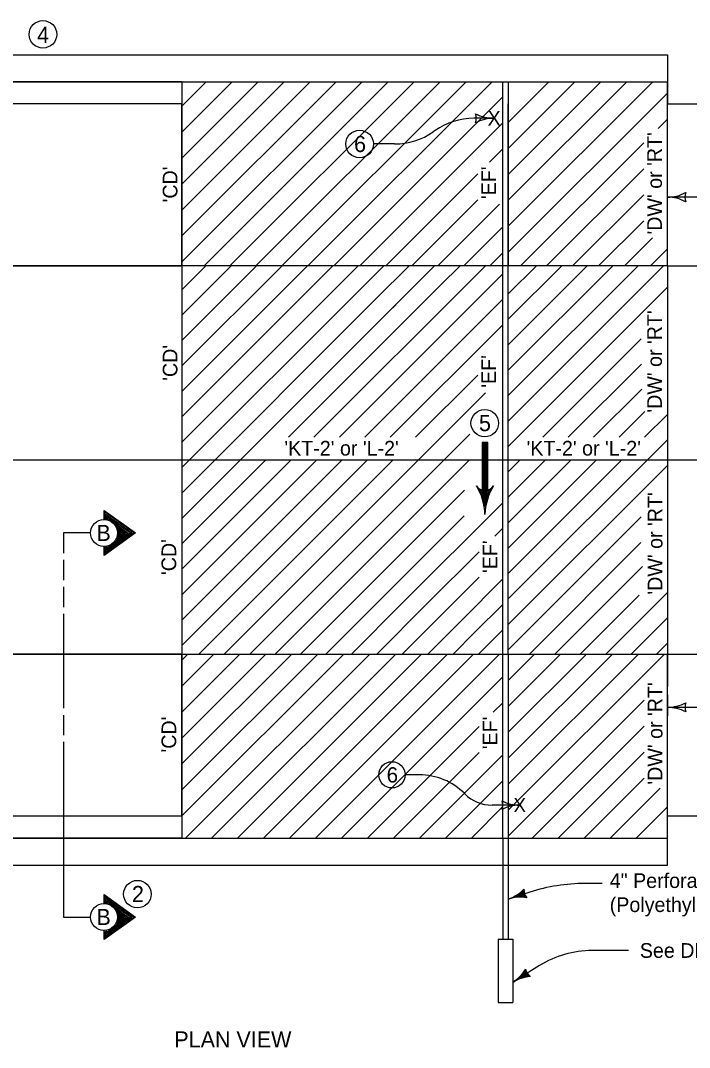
# Model space of a CAD drawing. Extents: x 10045 to 81668, y 6370 to 11018.
# Drawn here: x 14873 to 15638, y 6428 to 7602 of the extents above; entities that cross this region are included whole.
import ezdxf

# ---------------------------------------------------------------- set-up
doc = ezdxf.new("R2010")
doc.units = 0
for name, color, linetype in [('Alignment', 7, 'Continuous'), ('Default', 7, 'Continuous'), ('dsnStdLineWork', 7, 'Continuous')]:
    doc.layers.add(name, color=color, linetype=linetype)

msp = doc.modelspace()

# ---------------------------------------------------------------- linework, layer by layer
at = {"layer": 'Alignment'}
for p, q in [((15612.4, 7369.2), (15612.4, 7410.7)), ((15756.9, 7400.4), (15612.4, 7400.4)), ((15612.4, 7322), (15612.4, 6877.9)), ((15417, 6898.4), (15424.3, 6905.6)), ((14248, 6877.9), (15612.4, 6877.9)), ((15612.4, 6831.3), (15612.4, 6807.4)), ((15612.4, 6817), (15755.9, 6817)), ((14922.1, 6777.4), (14922.1, 6577.2)), ((15328.8, 6739.8), (15312.5, 6739.8)), ((15443.3, 6705.2), (15412, 6705.2)), ((15537.7, 6615.5), (15518.1, 6615.5)), ((15567.8, 6538.9), (15526.2, 6538.9)), ((15466.2, 6521.6), (15435.6, 6502.5))]:
    msp.add_line(p, q, dxfattribs=at)
for points in [[(14952.9, 7016.4), (14922.1, 7016.4), (14922.1, 6993.3)], [(14922.1, 6985.6), (14922.1, 6962.4)], [(14922.1, 6954.7), (14922.1, 6931.6)], [(14922.1, 6923.9), (14922.1, 6815.9)], [(14922.1, 6808.2), (14922.1, 6785.1)], [(14922.1, 6588.6), (14922.1, 6577.2), (14952.9, 6577.2)]]:
    msp.add_lwpolyline(points, dxfattribs=at)
for centre, radius, start, end in [((15328.8, 6666.4), 73.4, 45, 90), ((15412, 6749.2), 44.1, 225, 270), ((15518.1, 6409.9), 205.6, 90, 107.8594), ((15526.2, 6425.8), 113.1, 90, 122.0832)]:
    msp.add_arc(centre, radius, start, end, dxfattribs=at)
at = {"layer": 'Default'}
msp.add_line((14687.2, 7532.4), (15612.4, 7532.4), dxfattribs=at)
at = {"layer": 'dsnStdLineWork'}
for p, q in [((14724.2, 7563.3), (15612.4, 7563.3)), ((15612.4, 7563.3), (15612.4, 7507)), ((14687.2, 7532.4), (15057.3, 7532.4)), ((15057.3, 7532.4), (14687.2, 7532.4)), ((15057.3, 7532.4), (15057.3, 6877.9)), ((15057.3, 7326.3), (15263.5, 7532.4)), ((15057.3, 7356), (15233.8, 7532.4)), ((15057.3, 7385.7), (15204.1, 7532.4)), ((15057.3, 7415.4), (15174.4, 7532.4)), ((15057.3, 7445.1), (15144.7, 7532.4)), ((15057.3, 7474.8), (15115, 7532.4)), ((15057.3, 7504.5), (15085.3, 7532.4)), ((15082.7, 7322), (15293.2, 7532.4)), ((15112.4, 7322), (15322.9, 7532.4)), ((15142.1, 7322), (15352.6, 7532.4)), ((15171.8, 7322), (15382.3, 7532.4)), ((15201.5, 7322), (15412, 7532.4)), ((15424.3, 7322), (15424.3, 7532.4)), ((15430.4, 7532.4), (15430.4, 7322)), ((15430.4, 7367.1), (15595.7, 7532.4)), ((15430.4, 7396.8), (15566, 7532.4)), ((15430.4, 7426.5), (15536.3, 7532.4)), ((15430.4, 7456.2), (15506.6, 7532.4)), ((15430.4, 7485.9), (15476.9, 7532.4)), ((15612.4, 7322), (15612.4, 7532.4)), ((15430.4, 7337.4), (15612.4, 7519.4)), ((15057.3, 7507), (14687.3, 7507)), ((15057.3, 7322), (15057.3, 7507)), ((15057.3, 7321.9), (15057.3, 7507)), ((15231.2, 7322), (15424.3, 7515.1)), ((15424.3, 7322), (15424.3, 7507)), ((15430.4, 7322), (15430.4, 7507)), ((15612.4, 7507), (16123.2, 7507)), ((15612.4, 7322), (15612.4, 7507)), ((15260.9, 7322), (15424.3, 7485.4)), ((15414, 7490.6), (15391.2, 7490.6)), ((15601.7, 7479), (15612.4, 7489.7)), ((15347, 7476.7), (15344.7, 7475.1)), ((15300.5, 7461.2), (15276.3, 7461.2)), ((15444.6, 7322), (15585.3, 7462.6)), ((15409.1, 7440.5), (15424.3, 7455.7)), ((15290.6, 7322), (15395.8, 7427.2)), ((15474.3, 7322), (15585.3, 7432.9)), ((15504, 7322), (15585.3, 7403.2)), ((15320.3, 7322), (15395.8, 7397.5)), ((15350, 7322), (15420.3, 7392.3)), ((15379.7, 7322), (15424.3, 7366.6)), ((15533.7, 7322), (15585.3, 7373.5)), ((15563.4, 7322), (15595.2, 7353.7)), ((15612.4, 7322), (15612.4, 7359)), ((15593.1, 7322), (15612.4, 7341.2)), ((15409.4, 7322), (15424.3, 7336.9)), ((15612.4, 7322), (14201.3, 7322)), ((14687.3, 7321.9), (15057.3, 7321.9)), ((14687.3, 7321.9), (15057.3, 7321.9)), ((15057.3, 7294.6), (15084.7, 7322)), ((15057.3, 7265.5), (15113.7, 7322)), ((15057.3, 7236.4), (15142.8, 7322)), ((15057.3, 7207.4), (15171.9, 7322)), ((15057.3, 7178.3), (15201, 7322)), ((15057.3, 7149.2), (15230, 7322)), ((15057.3, 7120.1), (15259.1, 7322)), ((15057.3, 7321.9), (15057.3, 6877.9)), ((15261.9, 7295.7), (15288.2, 7322)), ((15279.3, 7284), (15317.3, 7322)), ((15305.3, 7280.9), (15346.3, 7322)), ((15353.6, 7300.2), (15375.4, 7322)), ((15396, 7313.4), (15404.5, 7322)), ((15424.3, 6877.9), (15424.3, 7322)), ((15430.4, 6877.9), (15430.4, 7322)), ((15430.4, 7289.8), (15462.6, 7322)), ((15430.4, 7260.7), (15491.7, 7322)), ((15430.4, 7231.6), (15520.8, 7322)), ((15430.4, 7144.4), (15608, 7322)), ((15430.4, 7202.5), (15549.9, 7322)), ((15430.4, 7173.5), (15578.9, 7322)), ((15612.4, 7322), (16158, 7322)), ((15208.3, 7125.8), (15396, 7313.4)), ((15237.4, 7125.8), (15424.3, 7312.7)), ((15057.3, 7091.1), (15261.9, 7295.7)), ((15179.2, 7125.8), (15353.6, 7300.2)), ((15430.4, 7115.3), (15612.4, 7297.3)), ((15057.3, 7062), (15279.3, 7284)), ((15266.5, 7125.8), (15424.3, 7283.6)), ((15170.8, 7146.5), (15305.3, 7280.9)), ((15305.3, 7280.9), (15298.4, 7274)), ((15295.5, 7125.8), (15424.3, 7254.5)), ((15470, 7125.8), (15582.4, 7238.2)), ((15056.9, 7212), (15057.3, 7212.5)), ((15499, 7125.8), (15582.7, 7209.4)), ((15324.6, 7125.8), (15395.8, 7197)), ((15105.8, 6877.9), (15404.5, 7176.6)), ((15528.1, 7125.8), (15583.2, 7180.8)), ((15557.2, 7125.8), (15586.8, 7155.4)), ((15057.3, 7032.9), (15170.8, 7146.5)), ((15586.3, 7125.8), (15612.4, 7151.9)), ((15134.9, 6877.9), (15386.5, 7129.5)), ((15403.9, 7065.2), (15403.9, 7119.8)), ((15430.4, 6940.9), (15612.4, 7122.8)), ((14687.2, 7099.9), (16203.5, 7099.9)), ((15057.3, 7003.8), (15153.4, 7099.9)), ((15057.3, 6974.8), (15182.5, 7099.9)), ((15057.3, 6945.7), (15211.5, 7099.9)), ((15057.3, 6916.6), (15240.6, 7099.9)), ((15131.6, 6961.9), (15269.7, 7099.9)), ((15146.2, 6947.3), (15298.8, 7099.9)), ((15163.9, 6877.9), (15386, 7099.9)), ((15430.4, 6999), (15531.4, 7099.9)), ((15430.4, 7028.1), (15502.3, 7099.9)), ((15430.4, 6969.9), (15560.4, 7099.9)), ((15430.4, 7057.2), (15473.2, 7099.9)), ((15430.4, 7086.2), (15444.1, 7099.9)), ((15430.4, 6911.8), (15612.4, 7093.7)), ((15193, 6877.9), (15380.5, 7065.4)), ((15400.8, 7065.3), (15400.8, 7065.3)), ((15407.2, 7065.4), (15407.2, 7065.4)), ((15309.4, 6936.2), (15424.3, 7051)), ((15293, 6948.8), (15380.1, 7035.9)), ((15430.4, 6882.7), (15582.4, 7034.7)), ((15415.2, 7012.8), (15424.3, 7021.9)), ((15454.7, 6877.9), (15582.2, 7005.4)), ((15337.9, 6935.6), (15397.1, 6994.8)), ((15483.8, 6877.9), (15583.9, 6978)), ((15360.4, 6929), (15397.1, 6965.7)), ((15057.3, 6887.5), (15131.6, 6961.9)), ((15222.1, 6877.9), (15297.1, 6952.9)), ((15376.9, 6916.4), (15424.3, 6963.8)), ((15076.7, 6877.9), (15146.2, 6947.3)), ((15512.8, 6877.9), (15580.2, 6945.3)), ((15541.9, 6877.9), (15612.4, 6948.4)), ((15251.2, 6877.9), (15309.4, 6936.2)), ((15280.2, 6877.9), (15337.9, 6935.6)), ((15309.3, 6877.9), (15364.8, 6933.4)), ((15392.4, 6902.8), (15424.3, 6934.7)), ((15338.4, 6877.9), (15380, 6919.5)), ((15571, 6877.9), (15612.4, 6919.3)), ((15367.5, 6877.9), (15392.4, 6902.8)), ((15396.5, 6877.9), (15417, 6898.4)), ((15600.1, 6877.9), (15612.4, 6890.2)), ((15057.3, 6877.9), (14687.3, 6877.9)), ((15057.3, 6877.9), (14687.3, 6877.9)), ((15057.3, 6877.9), (15057.3, 6692.9)), ((15057.3, 6877.9), (15057.3, 6692.9)), ((15057.3, 6877.9), (15057.3, 6667.4)), ((15057.3, 6722.5), (15212.7, 6877.9)), ((15057.3, 6752.2), (15183, 6877.9)), ((15057.3, 6811.6), (15123.6, 6877.9)), ((15057.3, 6841.3), (15093.9, 6877.9)), ((15057.3, 6871), (15064.2, 6877.9)), ((15057.3, 6781.9), (15153.3, 6877.9)), ((15057.3, 6692.8), (15057.3, 6877.9)), ((15057.4, 6692.9), (15242.4, 6877.9)), ((15061.6, 6667.4), (15272.1, 6877.9)), ((15091.3, 6667.4), (15301.8, 6877.9)), ((15121, 6667.4), (15331.5, 6877.9)), ((15150.7, 6667.4), (15361.2, 6877.9)), ((15180.4, 6667.4), (15390.9, 6877.9)), ((15210.1, 6667.4), (15420.6, 6877.9)), ((15424.3, 6667.4), (15424.3, 6877.9)), ((15430.4, 6877.9), (15430.4, 6667.4)), ((15430.4, 6699.3), (15609, 6877.9)), ((15430.4, 6729), (15579.4, 6877.9)), ((15430.4, 6758.7), (15549.7, 6877.9)), ((15430.4, 6788.4), (15520, 6877.9)), ((15430.4, 6818.1), (15490.3, 6877.9)), ((15430.4, 6847.8), (15460.6, 6877.9)), ((15430.4, 6877.5), (15430.9, 6877.9)), ((15612.4, 6877.9), (15612.4, 6840.9)), ((15612.4, 6877.9), (16158, 6877.9)), ((15612.4, 6692.9), (15612.4, 6877.9)), ((15612.4, 6667.4), (15612.4, 6877.9)), ((15239.8, 6667.4), (15424.3, 6851.9)), ((15430.4, 6669.6), (15585.9, 6825)), ((15413.4, 6811.3), (15424.3, 6822.2)), ((15269.5, 6667.4), (15397.1, 6795)), ((15458, 6667.4), (15585.9, 6795.3)), ((15299.2, 6667.4), (15397.1, 6765.3)), ((15487.7, 6667.4), (15585.9, 6765.6)), ((15328.9, 6667.4), (15424.3, 6762.8)), ((15358.6, 6667.4), (15424.3, 6733.1)), ((15517.4, 6667.4), (15585.9, 6735.9)), ((15547.1, 6667.4), (15604.3, 6724.6)), ((15388.3, 6667.4), (15424.3, 6703.4)), ((15576.8, 6667.4), (15612.4, 6703)), ((14687.3, 6692.8), (15057.3, 6692.8)), ((15612.4, 6692.9), (16123.2, 6692.9)), ((15612.4, 6636.6), (15612.4, 6692.9)), ((14687.2, 6667.4), (15612.4, 6667.4)), ((15424.3, 6667.4), (15424.3, 6551.7)), ((15430.4, 6667.4), (15430.4, 6551.7)), ((14724.2, 6636.6), (15612.4, 6636.6)), ((15455, 6605.6), (15430.4, 6597.7)), ((15430.4, 6597.7), (15449.3, 6603.7)), ((15419.1, 6551.7), (15435.6, 6551.7)), ((15419.1, 6551.7), (15419.1, 6479.3)), ((15435.6, 6551.7), (15435.6, 6479.3)), ((15435.6, 6502.5), (15452.3, 6513)), ((15419.1, 6479.3), (15435.6, 6479.3))]:
    msp.add_line(p, q, dxfattribs=at)
for points in [[(14687.3, 7514.7), (14687.2, 7514.7), (14687.2, 7532.4), (15057.3, 7532.4), (15057.3, 7507), (14687.3, 7507)], [(14687.3, 6685.1), (14687.3, 6692.8), (15057.3, 6692.8), (15057.3, 6667.4), (14687.2, 6667.4), (14687.2, 6685.1)]]:
    msp.add_lwpolyline(points, close=True, dxfattribs=at)
for points in [[(15424.3, 7322), (15424.3, 7322)], [(15430.4, 7322), (15430.4, 7322)], [(15407, 7065.3), (15407, 7119.8), (15400.8, 7119.8), (15400.8, 7065.3), (15406.1, 7065.5), (15406.3, 7119.1), (15401.4, 7118.9), (15401.6, 7066.5), (15405.3, 7066.4), (15405.5, 7118.3), (15402.2, 7118.2), (15402.2, 7067.2), (15404.5, 7067.1), (15404.8, 7117.7), (15402.9, 7117.6), (15403, 7067.9)], [(15411, 7066.8), (15407.3, 7064.5), (15401.9, 7064.2), (15397.2, 7066.2), (15400.6, 7058.2), (15403.3, 7048.8), (15403.9, 7046.1), (15405.3, 7052.9), (15408.7, 7062.8), (15410.2, 7065.7), (15398.8, 7064.6), (15403.7, 7050.1), (15408, 7064.3), (15400.1, 7063.7), (15403.8, 7053.8), (15406, 7062.9), (15401.4, 7063.3), (15403.5, 7057), (15404.9, 7061.8), (15402.7, 7062.1), (15403.4, 7059.8)], [(14968.4, 7031.8), (14968.4, 7042.1), (15004.3, 7016.4), (14968.4, 6990.7), (14968.4, 7001)], [(14969.4, 7000), (14969.3, 6992.5), (15002.4, 7016.4), (14969.2, 7040.4), (14969.4, 7032.5), (14970.8, 7032.2), (14970.3, 7037.9), (15000.2, 7016.4), (14970.3, 6994.6), (14970.6, 7000.1), (14971.7, 7000.4), (14971.6, 6996.7), (14998.2, 7016.5), (14971.5, 7035.3), (14972.1, 7032.1), (14973.2, 7031.8), (14973.1, 7032.9), (14996, 7016.2), (14972.7, 6998.6), (14973.9, 7000.6), (14993.9, 7016), (14981.6, 7025.8), (14982.4, 7024), (14991.9, 7015.9), (14982.7, 7009), (14983.6, 7010.8), (14989.9, 7015.7), (14983.6, 7021.2), (14984.2, 7018.8), (14988.3, 7015.6), (14984.1, 7012.4), (14984.3, 7014.1), (14986.7, 7015.6), (14984.4, 7017), (14984.6, 7015.5), (14985.3, 7015.6)], [(15424.3, 6877.9), (15424.3, 6877.9)], [(14968.4, 6592.6), (14968.4, 6602.9), (15004.3, 6577.2), (14968.4, 6551.5), (14968.4, 6561.8)], [(14969.4, 6560.8), (14969.3, 6553.3), (15002.4, 6577.2), (14969.2, 6601.2), (14969.4, 6593.3), (14970.8, 6592.9), (14970.3, 6598.7), (15000.2, 6577.2), (14970.3, 6555.4), (14970.6, 6560.9), (14971.7, 6561.1), (14971.6, 6557.5), (14998.2, 6577.3), (14971.5, 6596), (14972.1, 6592.9), (14973.2, 6592.5), (14973.1, 6593.6), (14996, 6577), (14972.7, 6559.4), (14973.9, 6561.4), (14993.9, 6576.8), (14981.6, 6586.6), (14982.4, 6584.8), (14991.9, 6576.7), (14982.7, 6569.7), (14983.6, 6571.6), (14989.9, 6576.5), (14983.6, 6582), (14984.2, 6579.6), (14988.3, 6576.4), (14984.1, 6573.2), (14984.3, 6574.9), (14986.7, 6576.3), (14984.4, 6577.7), (14984.6, 6576.3), (14985.3, 6576.3)], [(15450, 6600.1), (15448.2, 6603.4), (15447.8, 6607.2), (15444.2, 6603.8), (15438, 6600.1), (15445.7, 6600.8), (15449.3, 6600.4), (15447.5, 6603.2), (15447.1, 6605.6), (15444.7, 6603.3), (15441.3, 6601.2), (15445.6, 6601.3), (15447.9, 6601.3), (15446.6, 6604.2), (15444.2, 6602.1), (15446.6, 6602.2), (15446.3, 6603.2), (15445.4, 6602.5)], [(15453.9, 6509.6), (15451.3, 6512.4), (15450, 6515.9), (15447.4, 6511.8), (15442.3, 6506.7), (15449.6, 6509.2), (15453.2, 6509.7), (15450.8, 6512), (15449.8, 6514.2), (15448, 6511.5), (15445.3, 6508.6), (15449.4, 6509.7), (15451.6, 6510.3), (15449.6, 6512.7), (15447.8, 6510.2), (15450.1, 6510.8), (15449.6, 6511.7), (15448.9, 6510.8)]]:
    msp.add_lwpolyline(points, dxfattribs=at)
for centre, radius in [((14898.6, 7586.6), 15.7), ((15260.6, 7461.2), 15.7), ((15403.6, 7142), 15.7), ((14968.4, 7016.4), 15.4), ((15297.5, 6739.8), 15), ((15006.5, 6603.4), 15.7), ((14968.4, 6577.2), 15.4)]:
    msp.add_circle(centre, radius, dxfattribs=at)
for centre, radius, start, end in [((15376.8, 7490.6), 17.1, 342.2666, 17.7334), ((15414, 7535), 44.4, 241.9275, 270), ((15376.8, 7490.6), 17.1, 342.2666, 17.7334), ((15414, 7535), 44.4, 241.9275, 270), ((15391.2, 7413.5), 77.1, 90, 124.9993), ((15414, 7446.2), 44.4, 90, 118.0725), ((15414, 7446.2), 44.4, 90, 118.0725), ((15300.5, 7538.3), 77.1, 270, 304.9999), ((15612.4, 7444.8), 44.4, 270, 298.0725), ((15612.4, 7356), 44.4, 61.9275, 90), ((15649.6, 7400.4), 17.1, 162.2666, 197.7334), ((15403.9, 7076.5), 11.6, 211.7147, 328.2853), ((15337.6, 7035.6), 66.3, 1.6842, 31.7143), ((15470.1, 7035.6), 66.3, 148.2857, 178.3158), ((15612.4, 6861.6), 44.6, 270, 298.0725), ((15612.4, 6861.6), 44.6, 270, 298.0725), ((15612.4, 6772.3), 44.6, 61.9275, 90), ((15612.4, 6772.3), 44.6, 61.9275, 90), ((15649.8, 6817), 17.2, 162.2666, 197.7334), ((15649.8, 6817), 17.2, 162.2666, 197.7334), ((15407.9, 6705.2), 16.3, 342.2666, 17.7333), ((15443.3, 6747.4), 42.3, 241.9275, 270), ((15443.3, 6662.9), 42.3, 90, 118.0725), ((15417, 6639.3), 43.7, 287.8585, 315.9309), ((15465.3, 6608.9), 16.9, 180.1251, 215.5918), ((15443.8, 6556.1), 43.7, 79.786, 107.8585), ((15412.4, 6539.5), 43.7, 302.0841, 330.1566), ((15458.8, 6465.5), 43.7, 94.0116, 122.0841), ((15466.6, 6521.9), 16.9, 194.3508, 229.8175)]:
    msp.add_arc(centre, radius, start, end, dxfattribs=at)

# ---------------------------------------------------------------- texts
at = {"layer": 'Alignment'}
for s, height, p in [('4', 18.4, (14891.9, 7576.8)), ('X', 16.8, (15406.9, 7482.2)), ('6', 18.4, (15254.2, 7452)), ('5', 18.4, (15397, 7132.8)), ("'KT-2' or 'L-2'", 16.8, (15174.6, 7104.9)), ("'KT-2' or 'L-2'", 16.8, (15451.4, 7104.9)), ('B', 18.4, (14959.7, 7007.2)), ('6', 17.5, (15291.5, 6731)), ('X', 16, (15436.5, 6697.2)), ('4" Perforated Subdrain ', 16.8, (15546.5, 6610.4)), ('2', 18.4, (15000.3, 6594.3)), ('(Polyethylene, Corrugated Tubing)', 16.8, (15546.5, 6582.9)), ('B', 18.4, (14959.7, 6568)), ('See DR-306 for outlet details', 16.8, (15580.9, 6530.5)), ('PLAN VIEW', 18.37, (15048.8, 6428))]:
    msp.add_text(s, height=height, dxfattribs=at).set_placement(p)
for s, p in [("'DW' or 'RT'", (15606.1, 7357.7)), ("'CD'", (15052.3, 7394.4)), ("'EF'", (15416.6, 7398.2)), ("'DW' or 'RT'", (15606.1, 7154)), ("'CD'", (15052.3, 7190.4)), ("'EF'", (15416.6, 7182.5)), ("'DW' or 'RT'", (15606.7, 6945.9)), ("'CD'", (15050.9, 6968.3)), ("'EF'", (15417.9, 6970.6)), ("'DW' or 'RT'", (15606.7, 6728.6)), ("'CD'", (15050.9, 6765.3)), ("'EF'", (15417.9, 6769.1))]:
    msp.add_text(s, height=16.8, rotation=90, dxfattribs=at).set_placement(p)

doc.saveas('drawing.dxf')
